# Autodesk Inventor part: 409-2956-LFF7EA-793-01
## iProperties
Shininess: 64.0
Angle Display Precision: 2
Document Length Units: 11272
Document Angle Units: 11279
Document Time Units: 11290
Document Mass Units: 11286
Document Length Units Precision: 3
Document Angle Units Precision: 2
Compacted: True
Created: 2002-04
Part Number: 409-2956-LFF7EA-793-01
Description: INLET PIPE STAND ANGLE
Document SubType Name: Modeling
Designer: S. Boerckel
Mass: 1383.8 g
Surface Area: 585.555 cm^2
Volume: 176.281 cm^3
Density: 7.85 g/cm^3
Cost Center: 2 x 2 x 1/4 ANGLE
Material: ASTM A36
Engineer: S. Boerckel
User Status: SAW
Density: 0.0
Volumn: 0.0
Area: 0.0
PropertySet Name: Model Information
Control State: 0
Master: False
Checked Out: False
length: 11.500 in
SMR: =<COST CENTER> - <MATERIAL>
Author: S. Boerckel
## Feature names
1. Extrusion1
